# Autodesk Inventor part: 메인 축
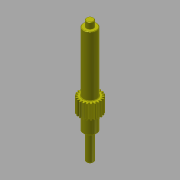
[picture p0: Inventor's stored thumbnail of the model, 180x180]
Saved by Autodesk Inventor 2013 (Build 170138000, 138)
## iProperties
Created: 2016-02
Part Number: 메인 축
Material: 강철, 연강
Document SubType Name: Modeling
Categories: <?xml version="1.0" encoding="UTF-16"?> <MemberInstance><Categories><FamilyTemplate><FamilyTemplateParameter ValueType="xs:double" Id="1" ObjectReferenceKey="da
Density: 7.86 g/cm^3
Mass: 181.397 g
Surface Area: 79.0018 cm^2
Volume: 23.0784 cm^3
Author: mdu
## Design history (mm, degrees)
sketch "Sketch1"
  geometry: C1 r 12 at (0, 0)
  constraints: 1 centre point
  dimensions: "d0" = 24 diameter of C1 (= da_da)
extrude "Extrusion1" new body sketch "Sketch1" distance "d1" = 20 (= da_b); taper "d2" = 0 deg
workplane "Work Plane2"
feature "피치 지름" dims "d4" = 10, "d5" = 0
workplane "Work Plane8"
workplane "Work Plane9"
chamfer "모따기1" distance "d49" = 1; stored, may be unused: second distance "d50" = 2, angle "d51" = 45 deg
sketch "스케치3"
  geometry: C1 r 7.5 at (0, 0); 1 further point
  constraints: 1 centre point, 1 coincident
  dimensions: "d52" = 15 diameter of C1
extrude "돌출2" join sketch "스케치3" distance "d53" = 66; taper "d54" = 0 deg
sketch "스케치4"
  geometry: C1 r 4 at (0, 0); 1 further point
  constraints: 1 centre point, 1 coincident
  dimensions: "d55" = 8 diameter of C1
extrude "돌출3" join sketch "스케치4" distance "d56" = 7; taper "d57" = 0 deg
sketch "스케치5"
  geometry: C1 r 7.5 at (0, 0) reference; C2 r 7.5 at (0, 0) reference; 1 further point
extrude "돌출4" join sketch "스케치5" distance "d62" = 16; taper "d63" = 0 deg
sketch "스케치6"
  geometry: C1 r 4 at (0, 0); 1 further point
  constraints: 1 centre point, 1 coincident
  dimensions: "d64" = 8 diameter of C1
extrude "돌출5" join sketch "스케치6" distance "d65" = 30; taper "d66" = 0 deg
chamfer "모따기2" distance "d58" = 0.5; stored, may be unused: second distance "d59" = 2, angle "d60" = 45 deg
fillet "모깎기1" dims "d61" = 0.5
feature "스퍼 기어" dims "da_b" = 20, "da_d" = 22, "da_aw" = 31, "da_da" = 24, "da_df" = 19.5, "da_dw" = 22, angle "da_beta" = 0 deg, "da_lefttooth" = 0, "da_righttooth" = 0
sketch "스케치7" dims "d68" = 18
  geometry: C1 r 0.25 at (0, -9); 2 further points
  constraints: 2 vertical alignment, 1 centre point, 1 coincident, 2 other
  dimensions: "d67" = 0.5 diameter of C1
extrude "돌출6" join sketch "스케치7" distance "d69" = 0.3; taper "d70" = 0 deg
feature "면 이동1"
feature "면 이동2"
feature "면 이동3"
body "Solid1"
sketch "Sketch2"
  geometry: C1 r 12 at (0, 0) reference; C2 r 11 at (0, 0)
  constraints: 1 centre point, 1 coincident
  dimensions: "d3" = 22 diameter of C2 (= da_dw)
body "Srf1"
node "투영된 루프1"
other parameters: "d16" = 31 (= da_aw), "d17" = 0, "d34" = 1.428 (computed from da_z), "d39" = 0, "d41" = 0, "d43" = 31 (= da_aw), "d46" = 31 (= da_aw), "d47" = 0, "d48" = 0
